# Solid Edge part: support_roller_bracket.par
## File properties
Title: Support roller bracket
Author: Abhinav Rai
Template: Normal.par
Last saved by: Rajat Kamboj
Revision: 21
Application: Solid Edge
Accuracy: 0.99
Material: aluminum
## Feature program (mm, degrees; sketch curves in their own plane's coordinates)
sketch for "unnamed Protrusion 1" #1 plane through (0, 0, 0) normal (0, -1, 0) x-axis (1, 0, 0)
  circle centre (0, -138.9237) radius 3.81
sketch for "unnamed Protrusion 1" #2 plane through (0, 0, 0) normal (0, -1, 0) x-axis (1, 0, 0)
  line (143.637, -99.9249) -> (-143.637, -99.9249)
  line (-143.637, -99.9249) -> (-143.637, -115.1647)
  line (-143.637, -115.1647) -> (-61.0846, -156.7704)
  line (-61.0846, -156.7704) -> (-61.0846, -162.9363)
  line (-61.0846, -162.9363) -> (61.0846, -162.9363)
  line (61.0846, -156.7704) -> (61.0846, -162.9363)
  line (143.637, -115.1647) -> (61.0846, -156.7704)
  line (143.637, -99.9249) -> (143.637, -115.1647)
  dimension (linear) = 143.637
extrude "unnamed Protrusion 1" add finite 101.6 symmetric
fillet "Round_1" radius 31.75
fillet "Round_2" radius 6.35
sketch for "unnamed Protrusion 2" plane through (0, 0, 67.2512) normal (1, 0, 0) x-axis (0, 1, 0)
  arc centre (-23.4135, -61.792) radius 19.05 from (-23.4135, -42.742) to (-42.405, -60.3002) ccw
  line (-50.8, -167.1761) -> (-42.405, -60.3002)
  line (-50.8, -167.1761) -> (50.8, -167.1761)
  line (45.7777, -60.8928) -> (50.8, -167.1761)
  arc centre (26.749, -61.792) radius 19.05 from (26.749, -42.742) to (45.7777, -60.8928) cw
  line (19.05, -42.742) -> (26.749, -42.742)
  line (19.05, -64.967) -> (19.05, -42.742)
  arc centre (0, -64.967) radius 19.05 from (-19.05, -64.967) to (19.05, -64.967) ccw
  line (-19.05, -42.742) -> (-19.05, -64.967)
  line (-23.4135, -42.742) -> (-19.05, -42.742)
extrude "unnamed Protrusion 2" add to key point symmetric
sketch for "ExtrudedCutout_1" plane through (0, 0, 0) normal (0, -1, 0) x-axis (1, 0, 0)
  line (-128.3193, 24.5092) -> (125.6319, 24.5092)
  line (125.6319, 24.5092) -> (125.6319, -99.9249)
  line (125.6319, -99.9249) -> (-128.3193, -99.9249)
  line (-128.3193, -99.9249) -> (-128.3193, 24.5092)
extrude "ExtrudedCutout_1" cut finite 203.2 symmetric
chamfer "Chamfer_1" setback 5.08
rib "Rib_1"  Thickness = 25.4 mm
mirror "unnamed Mirror 1" of "Rib_1" about plane through (0, 0, 0) normal (1, 0, 0)
rib "unnamed Rib 1"
sketch for "Hole_1" plane through (0.1259, 0, -162.9363) normal (0, 0, -1) x-axis (-1, 0, 0)
  hole centre (0.1259, 0) bore radius 25.4
hole "Hole_1" diameter 50.8 through
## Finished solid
Body 1: solid body, 55 faces, 142 edges, 86 vertices.
  Faces by surface: plane 38, cylinder 17
  Edges by curve: line 106, circle 34, intersection 2
Bounding box of the edges (mm): 379.121 x 101.600 x 187.446, from (-189.5605, -50.8, -162.9363) to (189.5605, 50.8, 24.5092).
Cylindrical faces by radius (mm): R3.81 x2, R6.35 x2, R19.05 x6, R25.4 x1, R31.75 x4, R55.372 x2
Planar faces by outward normal: +x 4, +y 5, +z 5, -x 4, -y 5, -z 1, oblique 14
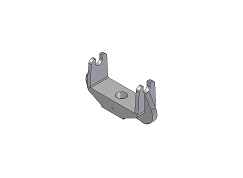
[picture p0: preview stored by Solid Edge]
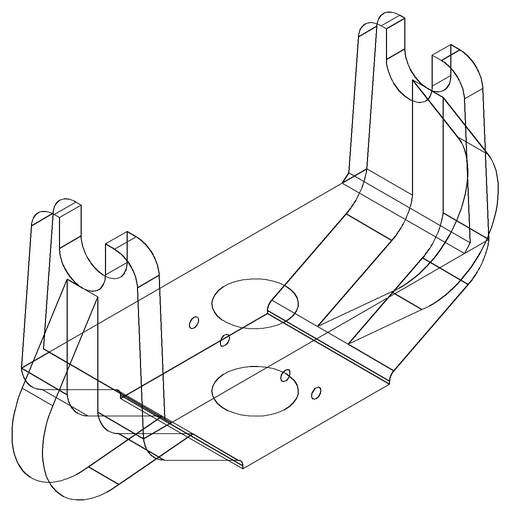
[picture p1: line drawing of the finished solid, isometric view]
